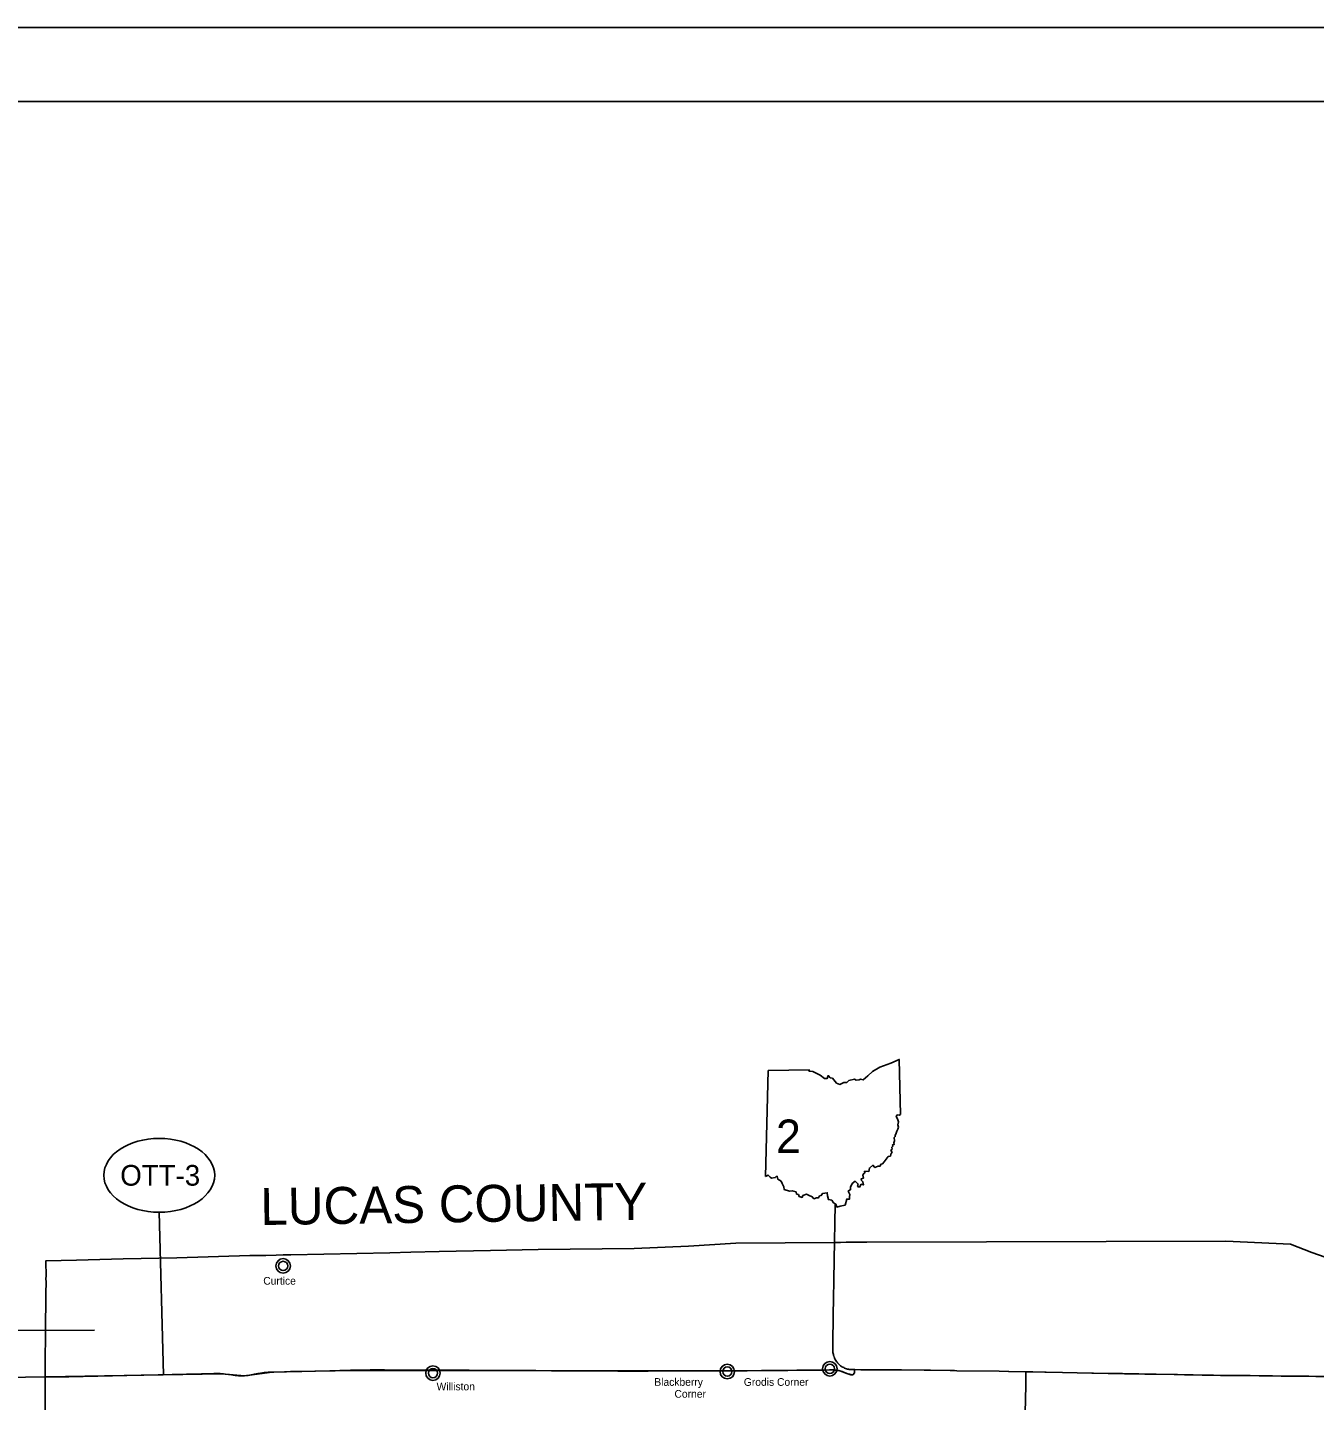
# Model space of a CAD drawing. Extents: x -82 to 873, y 0 to 440.
# Drawn here: x 90.7 to 264.9, y 253.6 to 440 of the extents above; entities that cross this region are included whole.
import ezdxf

# ---------------------------------------------------------------- set-up
doc = ezdxf.new("R2010")
doc.units = 0
for name, color, linetype in [('DV_X_Corp_Line', 7, 'Continuous'), ('DV_X_County_Line', 7, 'Continuous'), ('GM_P_US_Alignment', 7, 'Continuous'), ('GM_X_Adjacent_County_Text', 7, 'Continuous'), ('GM_X_County', 7, 'Continuous'), ('GM_X_Interstate_Route', 7, 'Continuous'), ('PV_P_Text', 7, 'Continuous'), ('SH_Border', 7, 'Continuous'), ('SH_Cut_Line', 7, 'Continuous'), ('SH_Data', 7, 'Continuous')]:
    doc.layers.add(name, color=color, linetype=linetype)

msp = doc.modelspace()

# ---------------------------------------------------------------- linework, layer by layer
at = {"layer": 'DV_X_Corp_Line'}
for centre, radius in [((125.3, 272.4), 0.982), ((125.3, 272.4), 0.623), ((185.42, 258.1), 0.982), ((199.3, 258.48), 0.982), ((199.3, 258.48), 0.623), ((145.58, 257.89), 0.982), ((145.58, 257.89), 0.623), ((185.42, 258.1), 0.623)]:
    msp.add_circle(centre, radius, dxfattribs=at)
at = {"layer": 'DV_X_County_Line'}
msp.add_lwpolyline([(73.63, 263.62), (99.78, 263.72)], dxfattribs=at)
at = {"layer": 'GM_P_US_Alignment'}
msp.add_lwpolyline([(93.16, 257.37), (117.02, 257.81), (120.09, 257.54), (123.82, 258.02), (131.61, 258.21), (154.68, 258.25), (178.91, 258.19), (192.56, 258.24), (199.66, 258.33), (200.67, 258.21), (201.62, 257.86), (202.41, 257.67), (202.63, 257.95), (202.65, 258.36)], dxfattribs=at)
at = {"layer": 'GM_X_County'}
msp.add_lwpolyline([(268.01, 273), (264.54, 274.23), (261.66, 275.34), (252.92, 275.74), (204.29, 275.63), (204.17, 275.63), (202.44, 275.6), (201.52, 275.6), (200.76, 275.59), (199.94, 275.57), (186.57, 275.49), (180.17, 275.05), (172.83, 274.75), (159.83, 274.62), (153.35, 274.48), (146.41, 274.33), (142.59, 274.25), (139.74, 274.17), (126.34, 273.91), (125.31, 273.88), (124.34, 273.86), (122.96, 273.82), (120.78, 273.79), (110.89, 273.51), (103.64, 273.34), (97.32, 273.18), (93.19, 273.09), (93.2, 270.9), (93.2, 270.89), (93.18, 270.85), (93.18, 270.8), (93.18, 270.76), (93.18, 270.7), (93.18, 270.65), (93.18, 270.56), (93.19, 270.49), (93.2, 270.41), (93.2, 270.22), (93.2, 269.94), (93.19, 268.99), (93.17, 267.09), (93.16, 266.25), (93.15, 265.83), (93.14, 265.46), (93.13, 264.56), (93.12, 263.99), (93.11, 262.8), (93.11, 262.39), (93.11, 261.68), (93.1, 261.04), (93.1, 260.3), (93.1, 259.72), (93.1, 259.43), (93.1, 258.66), (93.1, 258), (93.1, 257.37), (93.1, 257.26), (93.1, 256.28), (93.1, 256.04), (93.1, 255.54), (93.1, 254.72), (93.1, 252.91)], dxfattribs=at)
at = {"layer": 'GM_X_Interstate_Route'}
for points in [[(200.03, 280.69), (199.9, 273.24), (199.88, 272.42), (199.86, 271.27), (199.85, 270.24), (199.81, 268.19), (199.76, 265.6), (199.76, 265.13)], [(199.76, 265.13), (199.75, 265.01), (199.71, 262.52), (199.71, 262.36)], [(199.71, 262.36), (199.69, 261.33), (199.69, 261), (199.71, 260.84), (199.72, 260.68), (199.74, 260.55), (199.78, 260.39), (199.81, 260.27), (199.82, 260.23), (199.87, 260.07), (199.91, 259.99), (199.92, 259.96), (199.97, 259.84), (200.03, 259.73), (200.11, 259.59), (200.21, 259.45), (200.28, 259.35), (200.35, 259.27), (200.42, 259.19), (200.51, 259.1), (200.59, 259.03), (200.66, 258.96), (200.75, 258.89), (200.84, 258.83), (200.94, 258.76), (201.08, 258.68), (201.19, 258.63), (201.3, 258.58), (201.42, 258.53), (201.57, 258.48), (201.69, 258.44), (201.81, 258.42), (201.93, 258.4), (202.09, 258.38), (202.34, 258.37), (202.56, 258.37), (202.65, 258.36), (202.67, 258.36), (203.49, 258.35), (204.64, 258.34), (204.76, 258.34)], [(76.67, 257.1), (93.16, 257.37), (94.76, 257.39), (96.27, 257.41), (98.21, 257.45), (100.21, 257.49), (102.22, 257.53), (104.12, 257.58), (106.09, 257.62), (106.43, 257.62), (108.4, 257.67), (110.26, 257.7), (112.2, 257.74), (114.23, 257.78), (114.27, 257.78), (114.94, 257.8), (115.92, 257.82), (116.51, 257.83), (116.79, 257.82), (117.02, 257.81), (117.23, 257.79), (117.47, 257.75), (118.32, 257.64), (118.55, 257.6), (118.82, 257.57), (119.01, 257.55), (119.27, 257.53), (119.59, 257.53), (119.87, 257.53), (120.09, 257.54), (120.32, 257.56), (120.58, 257.59), (120.81, 257.63), (121.36, 257.73), (121.89, 257.83), (122.25, 257.9), (122.5, 257.94), (122.72, 257.97), (123, 257.99), (123.28, 258.01), (123.82, 258.02)], [(123.82, 258.02), (124.02, 258.03), (125.49, 258.07), (126.29, 258.1), (127.82, 258.13), (129.6, 258.17), (131.61, 258.21), (132.32, 258.22), (132.97, 258.24), (133.06, 258.24)], [(133.06, 258.24), (133.43, 258.25), (134.4, 258.27), (135.22, 258.29), (137.06, 258.32), (139.02, 258.33), (148.65, 258.31)], [(148.65, 258.28), (149.97, 258.27)], [(149.97, 258.27), (150.47, 258.27), (152.32, 258.26), (152.91, 258.26), (154.68, 258.25), (155.02, 258.25), (156.95, 258.23), (158.82, 258.23), (158.93, 258.23), (159.52, 258.23), (161.62, 258.22), (164.93, 258.2), (166.51, 258.19), (168.24, 258.18), (170.6, 258.16), (172.67, 258.16), (172.74, 258.16), (173.57, 258.16), (174.72, 258.17), (177.49, 258.19), (178.91, 258.19), (182.1, 258.2), (183.41, 258.21), (184.4, 258.21), (185.71, 258.22), (186.44, 258.22)], [(186.44, 258.22), (187.15, 258.22), (188.09, 258.22), (190.06, 258.23), (191.41, 258.23), (192.56, 258.24), (193.63, 258.25), (194.82, 258.28), (196.17, 258.28), (198.51, 258.31), (199.26, 258.32), (199.5, 258.33)], [(199.5, 258.33), (199.65, 258.33), (199.66, 258.33), (199.9, 258.32), (200.12, 258.3), (200.32, 258.28), (200.51, 258.25), (200.67, 258.21), (200.81, 258.17), (200.95, 258.12), (201.08, 258.07), (201.62, 257.86), (202.13, 257.66), (202.19, 257.65), (202.26, 257.64), (202.33, 257.65), (202.41, 257.67), (202.47, 257.7), (202.52, 257.74), (202.57, 257.8), (202.61, 257.88), (202.63, 257.95), (202.64, 258.01), (202.65, 258.36)], [(204.76, 258.34), (206.52, 258.33), (208.99, 258.32), (212.07, 258.29), (212.58, 258.28), (212.88, 258.28), (212.93, 258.28), (215.6, 258.24), (216.17, 258.23), (216.5, 258.22), (222.21, 258.14), (223.48, 258.12), (223.51, 258.12)], [(223.51, 258.12), (225.83, 258.08)], [(225.74, 252.94), (225.77, 253.96), (225.79, 254.83), (225.81, 255.77), (225.83, 256.76), (225.84, 257.17), (225.85, 257.88), (225.85, 257.92), (225.85, 257.95), (225.84, 257.99), (225.83, 258.03), (225.83, 258.08)], [(225.83, 258.08), (226.11, 258.08), (226.16, 258.08), (226.8, 258.06), (228.4, 258.03)], [(228.4, 258.03), (228.57, 258.03), (230.78, 257.98), (234.77, 257.9), (235.01, 257.9)], [(235.01, 257.9), (236.98, 257.86), (238.57, 257.83)], [(238.57, 257.83), (238.91, 257.82), (239.2, 257.81), (239.9, 257.8)], [(239.9, 257.8), (240.51, 257.79), (241.13, 257.78), (241.95, 257.77), (242.97, 257.75), (243.4, 257.74), (243.46, 257.74)], [(243.46, 257.74), (245.89, 257.7), (245.93, 257.7), (245.98, 257.7), (246.34, 257.69), (247.3, 257.67), (248.5, 257.65), (249.69, 257.63), (250.33, 257.62)], [(250.33, 257.62), (251.25, 257.6), (252.2, 257.59), (252.68, 257.58), (253.49, 257.57), (254.36, 257.56), (255.14, 257.56), (255.22, 257.56)], [(255.22, 257.56), (256.2, 257.55), (257.43, 257.54), (258.36, 257.53), (258.54, 257.52), (259.2, 257.52), (260.39, 257.5), (264.16, 257.46), (265.07, 257.45), (265.19, 257.45), (266.18, 257.45), (268.34, 257.46), (268.76, 257.46), (270.73, 257.46), (271.26, 257.47), (272.46, 257.47), (274.01, 257.48), (275.25, 257.48), (275.82, 257.48)]]:
    msp.add_lwpolyline(points, dxfattribs=at)
at = {"layer": 'PV_P_Text'}
msp.add_line((190.57, 284.48), (190.97, 298.84), dxfattribs=at)
msp.add_line((190.57, 284.48), (190.97, 298.84), dxfattribs=at)
for points in [[(190.97, 298.84), (196.54, 298.93), (196.46, 298.76), (196.98, 298.72), (197.54, 298.42), (198.01, 298.22), (198.59, 297.77), (198.94, 297.77), (199.08, 298.15), (199.35, 297.86), (199.66, 297.81), (200.21, 297.12), (200.66, 296.97), (201.19, 297.21), (201.59, 297.24), (201.89, 297.48), (202.65, 297.68), (202.86, 297.56), (203.27, 297.58), (203.47, 297.67), (203.83, 297.59), (204.45, 298.11), (205.09, 298.73), (206.07, 299.31), (207.54, 299.86), (208.7, 300.35), (208.87, 292.9)], [(190.97, 298.84), (196.54, 298.93), (196.46, 298.76), (196.98, 298.72), (197.54, 298.42), (198.01, 298.22), (198.59, 297.77), (198.94, 297.77), (199.08, 298.15), (199.35, 297.86), (199.66, 297.81), (200.21, 297.12), (200.66, 296.97), (201.19, 297.21), (201.59, 297.24), (201.89, 297.48), (202.65, 297.68), (202.86, 297.56), (203.27, 297.58), (203.47, 297.67), (203.83, 297.59), (204.45, 298.11), (205.09, 298.73), (206.07, 299.31), (207.54, 299.86), (208.7, 300.35), (208.87, 292.9)], [(208.87, 292.9), (208.7, 292.79), (208.43, 292.84), (208.26, 292.63), (208.48, 292.29), (208.58, 291.92), (208.49, 291.51), (208.58, 291.18), (208.52, 290.9), (208.35, 290.62), (208.29, 290.35), (208.15, 290.07), (208.16, 289.91), (208.03, 289.79), (208.05, 289.32), (207.98, 289.06), (208.01, 288.84), (207.78, 288.78), (207.84, 288.6), (207.7, 288.46), (207.73, 288.21), (207.57, 288.06), (207.72, 287.74), (207.6, 287.64), (207.49, 287.26), (207.21, 287.19), (206.64, 286.49), (206.44, 286.23), (206.22, 286.16), (206.1, 285.89), (205.82, 285.89), (205.4, 285.7), (205.13, 286.03), (204.66, 285.64), (204.6, 285.19), (204, 285.21), (204.03, 284.98), (203.89, 284.91), (203.77, 284.69), (203.84, 284.28), (203.56, 284.18), (203.59, 283.95), (203.77, 283.8), (203.85, 283.36), (203.56, 283.45), (203.31, 283.07), (203.06, 283.16), (203.14, 283.48), (202.72, 283.86), (202.32, 283.55), (202.11, 283.06), (202.1, 282.73), (201.8, 282.53), (202, 282.06), (201.96, 281.74), (201.97, 281.44), (201.59, 281.45), (201.37, 280.62)], [(208.87, 292.9), (208.7, 292.79), (208.43, 292.84), (208.26, 292.63), (208.48, 292.29), (208.58, 291.92), (208.49, 291.51), (208.58, 291.18), (208.52, 290.9), (208.35, 290.62), (208.29, 290.35), (208.15, 290.07), (208.16, 289.91), (208.03, 289.79), (208.05, 289.32), (207.98, 289.06), (208.01, 288.84), (207.78, 288.78), (207.84, 288.6), (207.7, 288.46), (207.73, 288.21), (207.57, 288.06), (207.72, 287.74), (207.6, 287.64), (207.49, 287.26), (207.21, 287.19), (206.64, 286.49), (206.44, 286.23), (206.22, 286.16), (206.1, 285.89), (205.82, 285.89), (205.4, 285.7), (205.13, 286.03), (204.66, 285.64), (204.6, 285.19), (204, 285.21), (204.03, 284.98), (203.89, 284.91), (203.77, 284.69), (203.84, 284.28), (203.56, 284.18), (203.59, 283.95), (203.77, 283.8), (203.85, 283.36), (203.56, 283.45), (203.31, 283.07), (203.06, 283.16), (203.14, 283.48), (202.72, 283.86), (202.32, 283.55), (202.11, 283.06), (202.1, 282.73), (201.8, 282.53), (202, 282.06), (201.96, 281.74), (201.97, 281.44), (201.59, 281.45), (201.37, 280.62)], [(201.37, 280.62), (200.72, 280.47), (200.26, 280.37), (200.11, 280.75), (199.78, 280.94), (199.57, 281.32), (199.11, 281.37), (199, 281.89), (198.95, 282.31), (198.31, 282.21), (198.14, 281.95), (197.91, 281.88), (197.78, 281.62), (197.48, 281.6), (197.15, 281.48), (196.93, 281.73), (196.4, 281.99), (196.15, 282.12), (195.65, 281.91), (195.54, 281.67), (195.14, 281.78), (195.04, 282.05), (194.8, 282.13), (194.74, 282.42), (194.22, 282.57), (193.82, 282.51), (193.12, 282.74), (193.08, 283.11), (192.84, 283.57), (192.71, 283.89), (192.27, 284.13), (192.18, 284.51), (192.03, 284.5), (191.9, 284.35), (191.41, 284.28), (191.21, 284.43), (190.94, 284.7), (190.57, 284.48)], [(201.37, 280.62), (200.72, 280.47), (200.26, 280.37), (200.11, 280.75), (199.78, 280.94), (199.57, 281.32), (199.11, 281.37), (199, 281.89), (198.95, 282.31), (198.31, 282.21), (198.14, 281.95), (197.91, 281.88), (197.78, 281.62), (197.48, 281.6), (197.15, 281.48), (196.93, 281.73), (196.4, 281.99), (196.15, 282.12), (195.65, 281.91), (195.54, 281.67), (195.14, 281.78), (195.04, 282.05), (194.8, 282.13), (194.74, 282.42), (194.22, 282.57), (193.82, 282.51), (193.12, 282.74), (193.08, 283.11), (192.84, 283.57), (192.71, 283.89), (192.27, 284.13), (192.18, 284.51), (192.03, 284.5), (191.9, 284.35), (191.41, 284.28), (191.21, 284.43), (190.94, 284.7), (190.57, 284.48)]]:
    msp.add_lwpolyline(points, dxfattribs=at)
at = {"layer": 'SH_Border'}
msp.add_lwpolyline([(30, 430), (670, 430), (670, 10), (30, 10)], close=True, dxfattribs=at)
at = {"layer": 'SH_Cut_Line'}
msp.add_lwpolyline([(0, 0), (680, 0), (680, 440), (0, 440)], close=True, dxfattribs=at)
at = {"layer": 'SH_Data'}
msp.add_line((108.53, 279.66), (109.1, 257.66), dxfattribs=at)
msp.add_ellipse((108.53, 284.66), major_axis=(7.5, 0), ratio=0.666667, dxfattribs=at)

# ---------------------------------------------------------------- texts
at = {"layer": 'DV_X_Corp_Line'}
for s, height, p in [('Curtice', 1.042, (122.61, 269.86)), ('Blackberry', 1.042, (175.54, 256.17)), ('Grodis Corner', 1.0417, (187.66, 256.17)), ('Williston', 1.042, (146.07, 255.56)), ('Corner', 1.042, (178.27, 254.56))]:
    msp.add_text(s, height=height, rotation=0.005, dxfattribs=at).set_placement(p)
at = {"layer": 'GM_X_Adjacent_County_Text'}
msp.add_text('LUCAS COUNTY', height=5, rotation=0.7972, dxfattribs=at).set_placement((122.25, 277.93))
at = {"layer": 'PV_P_Text'}
msp.add_text(' 2 ', height=4.528, rotation=0.005, dxfattribs=at).set_placement((190.33, 287.68))
at = {"layer": 'SH_Data'}
msp.add_text('OTT-3', height=2.8, dxfattribs=at).set_placement((103.25, 283.26))

doc.saveas('drawing.dxf')
